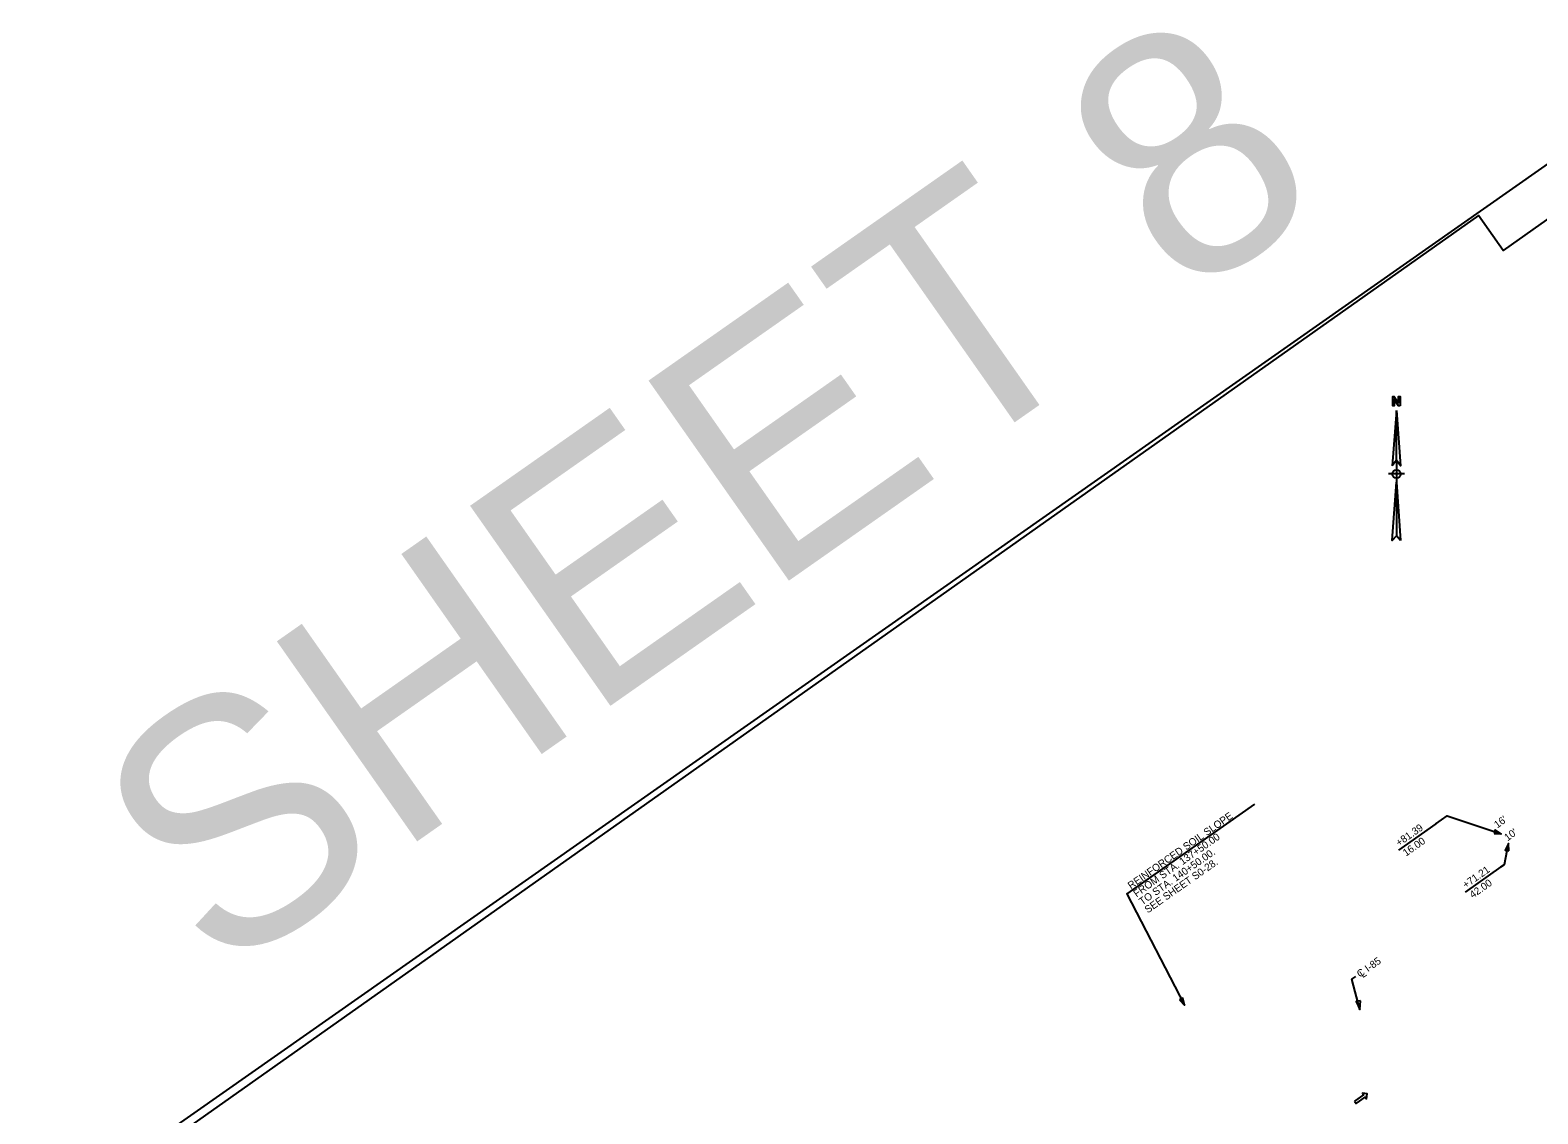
# Model space of a CAD drawing. Extents: x 1604963 to 1606883, y 1089540 to 1091304.
# Drawn here: x 1604963 to 1606197, y 1090417 to 1091304 of the extents above; entities that cross this region are included whole.
import ezdxf

# ---------------------------------------------------------------- set-up
doc = ezdxf.new("R2010")
doc.units = 0
for name, color, linetype in [('RD_DTM_BkLn1', 7, 'Continuous'), ('RD_EX_Bldg', 7, 'Continuous'), ('RD_EX_Fence_Other', 7, 'Continuous'), ('RD_EX_Misc', 7, 'Continuous'), ('RD_EX_Misc_Golf_Teebox', 7, 'Continuous'), ('RD_EX_RailRoad', 7, 'Continuous'), ('RD_EX_Road', 7, 'Continuous'), ('RD_EX_UT', 7, 'Continuous')]:
    doc.layers.add(name, color=color, linetype=linetype)

msp = doc.modelspace()

# ---------------------------------------------------------------- linework, layer by layer
at = {"layer": 'RD_DTM_BkLn1'}
msp.add_lwpolyline([(1606051, 1090502), (1606044.3, 1090526.9), (1606047.5, 1090529.2)], dxfattribs=at)
msp.add_lwpolyline([(1606051.4, 1090509.1), (1606048, 1090508.5), (1606051, 1090502)], close=True, dxfattribs=at)
at = {"layer": 'RD_EX_Bldg'}
msp.add_lwpolyline([(1604962.8, 1090323), (1606334.1, 1091284.8), (1606883.3, 1090501.8), (1605512, 1089539.9)], close=True, dxfattribs=at)
at = {"layer": 'RD_EX_Fence_Other'}
msp.add_lwpolyline([(1604962.8, 1090323), (1606334.1, 1091284.8), (1606883.3, 1090501.8), (1605512, 1089539.9)], close=True, dxfattribs=at)
at = {"layer": 'RD_EX_Misc'}
msp.add_lwpolyline([(1606046.5, 1090427.1), (1606047.9, 1090425.1), (1606055.4, 1090430.4), (1606056.4, 1090429), (1606057, 1090433), (1606053.1, 1090433.7), (1606054, 1090432.3)], close=True, dxfattribs=at)
at = {"layer": 'RD_EX_Misc_Golf_Teebox'}
for p, q in [((1605964.7, 1090670), (1605864.1, 1090599.4)), ((1606113, 1090653.9), (1606082.5, 1090632.5)), ((1606166.4, 1090618.7), (1606137.1, 1090598.2))]:
    msp.add_line(p, q, dxfattribs=at)
for points in [[(1605964.7, 1090670), (1605860.3, 1090596.8), (1605907.4, 1090505.6)], [(1606113, 1090653.9), (1606122.4, 1090660.5), (1606166.7, 1090645.9)], [(1606166.4, 1090618.7), (1606169.2, 1090620.6), (1606172.6, 1090637.8)]]:
    msp.add_lwpolyline(points, dxfattribs=at)
for points in [[(1606160.7, 1090646.2), (1606166.7, 1090645.9), (1606161.7, 1090649.2)], [(1606172.9, 1090631.8), (1606172.6, 1090637.8), (1606169.9, 1090632.4)], [(1605903.3, 1090510), (1605907.4, 1090505.6), (1605906.1, 1090511.4)]]:
    msp.add_lwpolyline(points, close=True, dxfattribs=at)
at = {"layer": 'RD_EX_RailRoad'}
for p, q in [((1606080.8, 1090992.2), (1606077.4, 1090946.9)), ((1606080.8, 1090951.6), (1606077.4, 1090946.9)), ((1606080.8, 1090951.6), (1606080.8, 1090933.7)), ((1606087.4, 1090940.3), (1606074.4, 1090940.3)), ((1606080.8, 1090933.7), (1606084.3, 1090885.9)), ((1606084.3, 1090885.9), (1606080.8, 1090889.7))]:
    msp.add_line(p, q, dxfattribs=at)
msp.add_lwpolyline([(1606083.8, 1090996.1), (1606082.5, 1090996.1), (1606079.1, 1091001.5), (1606079.1, 1091000.7), (1606079.1, 1090996.1), (1606077.9, 1090996.1), (1606077.9, 1091003.6), (1606079.1, 1091003.6), (1606082.5, 1090998.6), (1606082.5, 1090999), (1606082.5, 1091003.6), (1606083.8, 1091003.6), (1606083.8, 1090996.1)], dxfattribs=at)
for points in [[(1606080.8, 1090992.2), (1606084.3, 1090946.9), (1606080.8, 1090951.6)], [(1606080.8, 1090933.7), (1606080.8, 1090889.7), (1606077.4, 1090885.9)]]:
    msp.add_lwpolyline(points, close=True, dxfattribs=at)
msp.add_circle((1606080.9, 1090940.3), 3.45, dxfattribs=at)
at = {"layer": 'RD_EX_UT'}
msp.add_lwpolyline([(1605233.6, 1090111), (1605405.8, 1089865.4), (1605593.1, 1089598.4), (1606815.9, 1090456.1), (1606682.3, 1090657.8), (1606533, 1090870.5), (1606535.9, 1090871.8), (1606406.7, 1091049.1), (1606294.2, 1091212.3), (1606168.2, 1091123.2), (1606148, 1091151.8), (1605049.4, 1090375.5)], close=True, dxfattribs=at)
msp.add_lwpolyline([(1605233.6, 1090111), (1605405.8, 1089865.4), (1605593.1, 1089598.4), (1606815.9, 1090456.1), (1606682.3, 1090657.8), (1606533, 1090870.5), (1606535.9, 1090871.8), (1606406.7, 1091049.1), (1606294.2, 1091212.3), (1606168.2, 1091123.2), (1606148, 1091151.8), (1605049.4, 1090375.5)], close=True, dxfattribs=at)

# ---------------------------------------------------------------- texts
at = {"layer": 'RD_DTM_BkLn1'}
for s, p in [('C I-85', (1606051, 1090527.9)), ('L', (1606053.4, 1090527.6))]:
    msp.add_text(s, height=6, rotation=35.0535, dxfattribs=at).set_placement(p)
at = {"layer": 'RD_EX_Misc_Golf_Teebox'}
for s, rotation, p in [('REINFORCED SOIL SLOPE', 35.0485, (1605863.6, 1090600.3)), ('+81.39', 35.0468, (1606083, 1090635.3)), ("16'", 36.0638, (1606163.4, 1090650.1)), ("10'", 36.0638, (1606171.8, 1090639.6)), ('FROM STA. 137+50.00', 35.0485, (1605868.2, 1090593.7)), ('16.00', 35.0468, (1606088.7, 1090627.1)), ('TO STA. 140+50.00.', 35.0485, (1605872.8, 1090587.2)), ('SEE SHEET S0-28.', 35.0485, (1605877.4, 1090580.6)), ('+71.21', 35.0468, (1606137.6, 1090600.9)), ('42.00', 35.0468, (1606143.3, 1090592.8))]:
    msp.add_text(s, height=6, rotation=rotation, dxfattribs=at).set_placement(p)
at = {"layer": 'RD_EX_Road'}
msp.add_text('SHEET 8', height=200, rotation=35.0468, dxfattribs=at).set_placement((1605115.5, 1090524.6))

doc.saveas('drawing.dxf')
